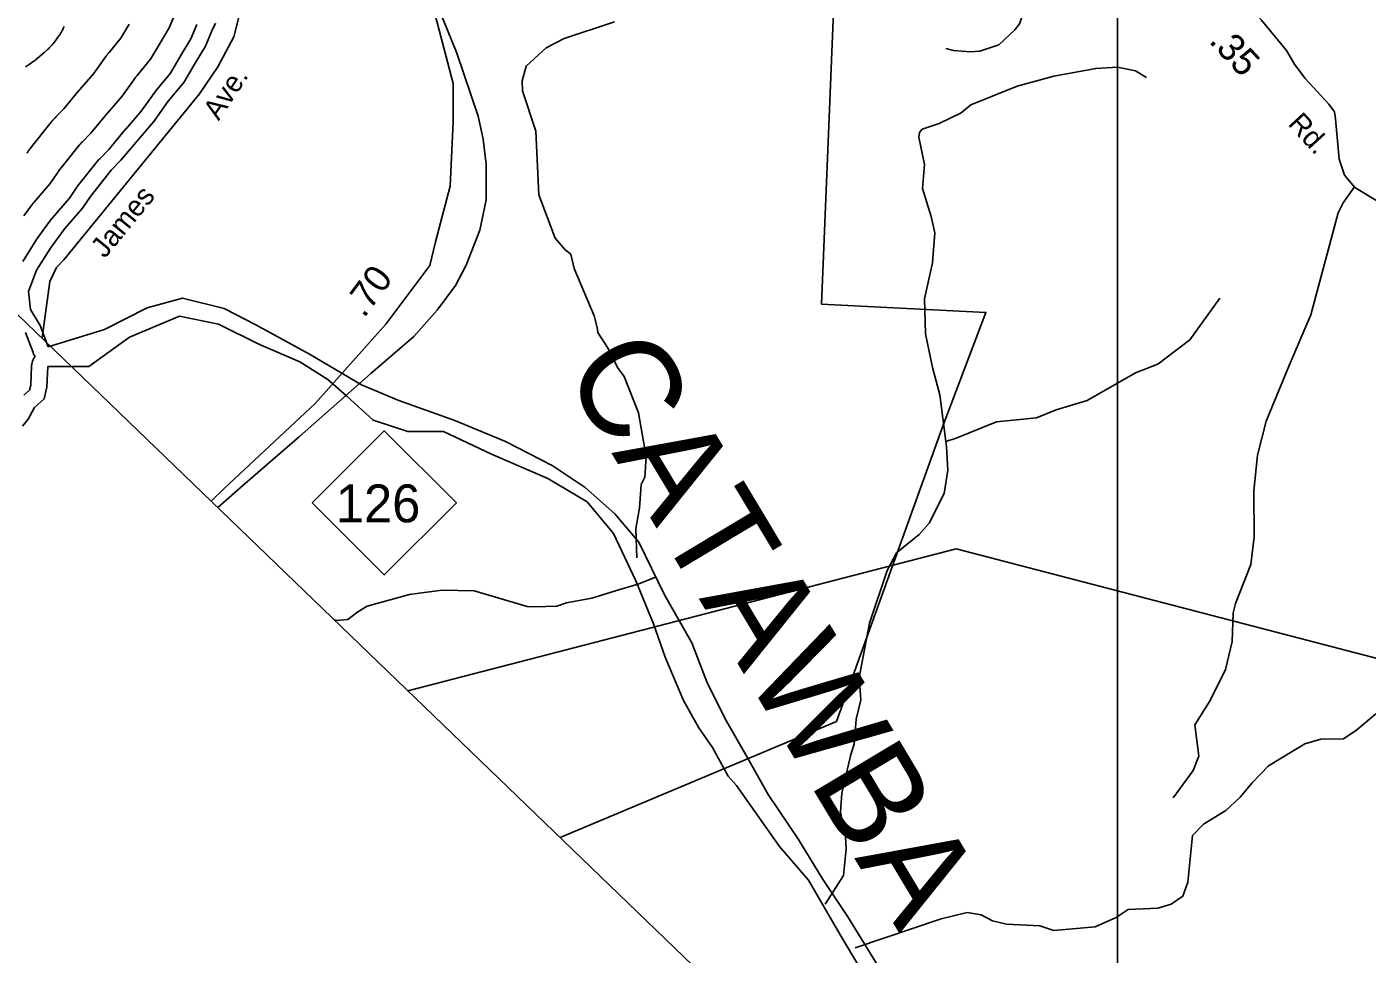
# Model space of a CAD drawing. Extents: x 1113032 to 1302912, y 664689 to 832535.
# Drawn here: x 1142627 to 1148822, y 731794 to 736082 of the extents above; entities that cross this region are included whole.
import ezdxf

# ---------------------------------------------------------------- set-up
doc = ezdxf.new("R2010")
doc.units = 0
for name, color, linetype in [('Exist Boundary Land Use Park State Division NC Parks and Recreation', 7, 'Continuous'), ('Exist Boundary Political CountyLine', 7, 'Continuous'), ('Exist Hydrographic Buffer Line', 7, 'Continuous'), ('Exist Hydrographic Lake Shore', 7, 'Continuous'), ('Exist Hydrographic Misc Water Feature', 7, 'Continuous'), ('Exist Hydrographic River Shore', 7, 'Continuous'), ('Exist Road Non-System Type 51', 7, 'Continuous'), ('Exist Road Non-System Type 51 Label', 7, 'Continuous'), ('Exist Road Primary NC Attributed', 7, 'Continuous'), ('Exist Road Primary NC Mileage Hundredths English Label', 7, 'Continuous'), ('Exist Road Primary NC Shield CELL', 7, 'Continuous'), ('Exist Road Primary NC Shield Number Label', 7, 'Continuous'), ('Exist Road Secondary Mileage Hundredths English Label', 7, 'Continuous'), ('Exist Road Secondary Type 51 Attributed', 7, 'Continuous'), ('Exist Road Secondary Type 51 Label', 7, 'Continuous'), ('Exist Utilities Electrical Transmission Line', 7, 'Continuous'), ('Map Preparation Inset Cut Line', 7, 'Continuous')]:
    doc.layers.add(name, color=color, linetype=linetype)

msp = doc.modelspace()

# ---------------------------------------------------------------- linework, layer by layer
at = {"layer": 'Exist Boundary Land Use Park State Division NC Parks and Recreation'}
for points in [[(1146388.6, 736979.2), (1146300.2, 734800.2), (1147059.9, 734761.5), (1146861.6, 734240.6), (1146368.8, 732870.4), (1145091.6, 732333.9)], [(1143478.9, 733889.6), (1143539.3, 733947.8), (1143959.8, 734341.2), (1144285.5, 734707.5), (1144489, 734978.9), (1144516, 735087.4), (1144583.9, 735345.1), (1144597.6, 735643.6), (1144597.6, 735820), (1144516, 736132)]]:
    msp.add_lwpolyline(points, dxfattribs=at)
at = {"layer": 'Exist Boundary Political CountyLine'}
msp.add_lwpolyline([(1114483.4, 761940.5), (1121830, 755020.9), (1129762.4, 747574.8), (1131998.8, 745469.7), (1132534.3, 744969.6), (1136601.4, 740850.7), (1137713.1, 739712.4), (1140850.4, 736412.5), (1141222.5, 736061.4), (1141222.5, 736061.4), (1142712.2, 734629.3), (1146816.8, 730669.7), (1148404.8, 729149.7)], dxfattribs=at)
at = {"layer": 'Exist Hydrographic Buffer Line'}
for points in [[(1142612.6, 735207.6), (1142651.1, 735260.2), (1142651.8, 735261.2), (1142652.5, 735262.1), (1142654.4, 735264.5), (1142655.8, 735266.3), (1142657.2, 735268.1), (1142659.2, 735270.5), (1142659.9, 735271.3), (1142660.7, 735272.2), (1142735.1, 735358.1), (1142765.5, 735403), (1142766.1, 735403.9), (1142766.7, 735404.7), (1142768.3, 735407.1), (1142769.6, 735408.8), (1142770.8, 735410.5), (1142772.6, 735412.8), (1142773.2, 735413.6), (1142773.9, 735414.5), (1142870.6, 735536.2), (1142871.5, 735537.3), (1142872.4, 735538.5), (1142874.9, 735541.5), (1142876.8, 735543.7), (1142878.8, 735545.9), (1142881.5, 735548.7), (1142882.5, 735549.8), (1142883.5, 735550.9), (1142922.7, 735590.9), (1142996.9, 735680), (1142997, 735680.2), (1142997.2, 735680.4), (1142997.6, 735680.9), (1142998, 735681.3), (1142998.3, 735681.7), (1142998.7, 735682.2), (1142998.9, 735682.4), (1142999.1, 735682.6), (1143066.7, 735760.9), (1143128.7, 735847.2), (1143129.2, 735847.9), (1143129.8, 735848.7), (1143131.3, 735850.7), (1143132.4, 735852.2), (1143133.6, 735853.7), (1143135.2, 735855.6), (1143135.7, 735856.4), (1143136.3, 735857.1), (1143199, 735933), (1143244.5, 736009.5), (1143284.7, 736077.7), (1143309.8, 736136.8)], [(1142607.6, 734996.6), (1142672, 735098.8), (1142673.4, 735101), (1142674.9, 735103.1), (1142702.9, 735141.4), (1142702.9, 735141.4), (1142703, 735141.4), (1142741.5, 735194.1), (1142743.4, 735196.5), (1142745.3, 735198.9), (1142824.1, 735289.8), (1142858.2, 735340.2), (1142859.9, 735342.5), (1142861.6, 735344.8), (1142958.3, 735466.6), (1142960.8, 735469.6), (1142963.5, 735472.4), (1143005.9, 735515.7), (1143083, 735608.4), (1143083.4, 735608.9), (1143083.9, 735609.4), (1143154.7, 735691.5), (1143219.6, 735781.8), (1143221.1, 735783.8), (1143222.7, 735785.8), (1143290.9, 735868.3), (1143340.8, 735952.4), (1143384.9, 736027.1), (1143412.9, 736093.1)], [(1142799.4, 736083.4), (1142798.3, 736081), (1142795.1, 736074.5), (1142792.7, 736069.7), (1142790.1, 736064.9), (1142786.6, 736058.7), (1142785.2, 736056.4), (1142783.8, 736054), (1142778.8, 736045.8), (1142777.4, 736043.5), (1142775.9, 736041.3), (1142772, 736035.2), (1142769, 736030.8), (1142765.8, 736026.4), (1142761.5, 736020.7), (1142759.9, 736018.5), (1142758.2, 736016.4), (1142752.2, 736008.9), (1142750.5, 736006.8), (1142748.7, 736004.7), (1142744, 735999.3), (1142740.5, 735995.2), (1142736.8, 735991.3), (1142731.7, 735986.2), (1142729.9, 735984.2), (1142727.9, 735982.4), (1142721, 735975.7), (1142720, 735974.7), (1142719, 735973.8), (1142716.4, 735971.4), (1142714.4, 735969.5), (1142712.4, 735967.8), (1142709.7, 735965.4), (1142708.7, 735964.5), (1142707.6, 735963.6), (1142671.7, 735933.2), (1142670.6, 735932.3), (1142669.5, 735931.3), (1142666.5, 735928.9), (1142664.2, 735927.1), (1142662, 735925.4), (1142658.9, 735923), (1142657.8, 735922.2), (1142656.6, 735921.3), (1142648.4, 735915.2), (1142646, 735913.6), (1142643.7, 735911.9), (1142637.3, 735907.6), (1142632.5, 735904.4), (1142627.6, 735901.4), (1142621, 735897.6)], [(1142626.6, 735497.5), (1142626.8, 735497.8), (1142627.4, 735498.7), (1142627.8, 735499.3), (1142628.3, 735500), (1142628.9, 735500.9), (1142629.1, 735501.2), (1142629.4, 735501.5), (1142631, 735503.9), (1142631.5, 735504.5), (1142631.9, 735505.2), (1142633.2, 735506.9), (1142634.1, 735508.2), (1142635.1, 735509.5), (1142636.3, 735511.2), (1142636.8, 735511.8), (1142637.3, 735512.5), (1142639, 735514.7), (1142639.3, 735515), (1142639.5, 735515.4), (1142640.2, 735516.2), (1142640.7, 735516.8), (1142641.2, 735517.5), (1142641.8, 735518.3), (1142642.1, 735518.6), (1142642.3, 735518.9), (1142739, 735640.7), (1142739.3, 735641.1), (1142739.7, 735641.5), (1142740.6, 735642.7), (1142741.3, 735643.5), (1142742, 735644.4), (1142742.9, 735645.5), (1142743.3, 735645.9), (1142743.6, 735646.4), (1142746.1, 735649.4), (1142746.9, 735650.2), (1142747.6, 735651), (1142749.5, 735653.3), (1142750.9, 735654.9), (1142752.4, 735656.5), (1142754.4, 735658.7), (1142755.1, 735659.5), (1142755.8, 735660.3), (1142758.5, 735663.2), (1142758.9, 735663.6), (1142759.3, 735664), (1142760.3, 735665.1), (1142761, 735665.9), (1142761.8, 735666.7), (1142762.8, 735667.7), (1142763.2, 735668.1), (1142763.6, 735668.5), (1142798, 735703.6), (1142867.7, 735787.4), (1142867.8, 735787.5), (1142867.8, 735787.6), (1142868, 735787.8), (1142868.1, 735787.9), (1142868.2, 735788.1), (1142868.4, 735788.2), (1142868.5, 735788.3), (1142868.5, 735788.4), (1142869, 735788.9), (1142869.1, 735789.1), (1142869.2, 735789.2), (1142869.5, 735789.6), (1142869.8, 735789.9), (1142870, 735790.2), (1142870.3, 735790.5), (1142870.5, 735790.7), (1142870.6, 735790.8), (1142871, 735791.3), (1142871.1, 735791.4), (1142871.1, 735791.5), (1142871.3, 735791.7), (1142871.4, 735791.8), (1142871.5, 735792), (1142871.7, 735792.1), (1142871.8, 735792.2), (1142871.8, 735792.3), (1142934.6, 735865.1), (1142992.3, 735945.3), (1142992.5, 735945.6), (1142992.7, 735945.9), (1142993.3, 735946.6), (1142993.7, 735947.2), (1142994.1, 735947.7), (1142994.7, 735948.5), (1142994.9, 735948.8), (1142995.1, 735949.1), (1142996.6, 735951.1), (1142997, 735951.6), (1142997.4, 735952.2), (1142998.6, 735953.7), (1142999.4, 735954.8), (1143000.3, 735955.9), (1143001.4, 735957.4), (1143001.9, 735958), (1143002.3, 735958.5), (1143003.9, 735960.5), (1143004.1, 735960.7), (1143004.3, 735961), (1143004.9, 735961.7), (1143005.3, 735962.3), (1143005.8, 735962.8), (1143006.4, 735963.6), (1143006.6, 735963.8), (1143006.8, 735964.1), (1143061.2, 736029.9), (1143099.9, 736095.1)], [(1142613.1, 734379.7), (1142639.5, 734402.4), (1142644.8, 734426), (1142649.1, 734515.3), (1142649.8, 734522.7), (1142651.3, 734529.9), (1142653.4, 734536.9), (1142656.2, 734543.7), (1142659.7, 734550.2), (1142663.8, 734556.3), (1142665.1, 734557.9), (1142661.9, 734562.5), (1142658.3, 734568.9), (1142655.4, 734575.7), (1142620.5, 734668.6)]]:
    msp.add_lwpolyline(points, dxfattribs=at)
at = {"layer": 'Exist Hydrographic Lake Shore'}
for points in [[(1143498.4, 736099.6), (1143482, 736063.8), (1143452, 735993.2), (1143405.4, 735914.2), (1143352.4, 735825), (1143280.5, 735738), (1143213.7, 735645.1), (1143140.7, 735560.4), (1143061.6, 735465.4), (1143017, 735419.9), (1142920.3, 735298.2), (1142883.7, 735244.1), (1142802, 735149.8), (1142763.5, 735097.1), (1142735.5, 735058.8), (1142671.1, 734956.6), (1142633.9, 734858.1), (1142643.6, 734774.5), (1142688.2, 734701.7), (1142725.6, 734602)], [(1142724, 734511.7), (1142719.4, 734416), (1142707.3, 734361.8), (1142662, 734322.8), (1142633.2, 734267.6), (1142607.4, 734236.4)]]:
    msp.add_lwpolyline(points, dxfattribs=at)
at = {"layer": 'Exist Hydrographic Misc Water Feature'}
for p, q in [((1146922.4, 734179.6), (1146874.7, 734164.2)), ((1146853.5, 731958), (1146454.7, 731823.6))]:
    msp.add_line(p, q, dxfattribs=at)
for points in [[(1145342.6, 736105.8), (1145110.3, 736028.6), (1145026.8, 735985), (1144934.3, 735899.7), (1144916.2, 735832.2), (1144917, 735786.2), (1144979.5, 735600.2), (1144992.8, 735305.6), (1145068.9, 735105.2), (1145115.4, 735051.8), (1145140.7, 735031), (1145156.9, 734964.4), (1145248.4, 734745.6), (1145262.7, 734691.2), (1145266.1, 734669.1), (1145314, 734595.6), (1145357.4, 734506.3), (1145388.2, 734465.3), (1145453.2, 734297.3), (1145489.3, 734094.1), (1145482.6, 734000.2), (1145465.5, 733966.7), (1145458.3, 733856.8), (1145441.5, 733763.2), (1145446.7, 733627)], [(1147802.1, 735847.4), (1147750.9, 735878.8), (1147667.4, 735895.3), (1147567.2, 735889.9), (1147374.1, 735853.5), (1147204.7, 735808.5), (1146990.4, 735720.8)], [(1146990.4, 735720.8), (1146945.3, 735684.2), (1146843.8, 735635.2), (1146765.1, 735609.5), (1146752.5, 735593.7), (1146749.9, 735571.9), (1146776.1, 735445), (1146766.9, 735335.2), (1146807.1, 735205.9), (1146822.8, 735129.4), (1146812.8, 734991.6), (1146775.8, 734824.5), (1146781, 734662.3), (1146812.4, 734507.2), (1146846.7, 734380.2), (1146874.7, 734164.2)], [(1148141.6, 734827.2), (1148002, 734634.7), (1147854.7, 734522.8), (1147751.6, 734482.2), (1147527.7, 734354.6), (1147384.5, 734310.6), (1147293.4, 734274.7), (1147108.7, 734256.2), (1146922.4, 734179.6)], [(1146874.7, 734164.2), (1146877.6, 734141.1), (1146884.4, 734032.8), (1146867.3, 733925.2), (1146797.1, 733787.2), (1146751.5, 733734.5), (1146647, 733649.6), (1146602.6, 733568.8), (1146521.3, 733325), (1146474, 733074.3), (1146480.9, 732970), (1146460.1, 732880.5), (1146450.7, 732764.7), (1146435.3, 732717.2), (1146393.9, 732538.2), (1146387.5, 732450.4), (1146397.7, 732394.1), (1146409, 732365.7), (1146414.4, 732281.5), (1146400.7, 732157.8), (1146317, 732025)], [(1145531.8, 733538.2), (1145451.9, 733504.7), (1145367.1, 733481.2), (1145237.9, 733441.1), (1145121.2, 733418.5), (1145076.7, 733403.8), (1144976.5, 733400.7), (1144938.6, 733401.8), (1144694.5, 733475.1), (1144544.5, 733477.6), (1144395.8, 733457.9), (1144200.1, 733403.6), (1144157.3, 733376.9), (1144110.1, 733342.3), (1144056, 733337.9), (1144048.6, 733340)], [(1148861.7, 732905.8), (1148773.5, 732832), (1148712.2, 732789.8), (1148608.3, 732788.6), (1148533.5, 732767.1), (1148366.5, 732665.4), (1148290.3, 732587.3), (1148234.4, 732521.1), (1148168.5, 732459.3), (1148064.7, 732395.7), (1148015.2, 732343.4), (1147993.1, 732128), (1147969.2, 732062), (1147916.2, 732026.1), (1147853.7, 732007.7), (1147717.3, 732001.4), (1147662.4, 731964.8), (1147565.1, 731921.6), (1147374.3, 731903.2), (1147309, 731925.1), (1147155.1, 731933.1), (1147089.4, 731949.1), (1147038.2, 731976.4), (1146972.5, 731986.8), (1146853.5, 731958)]]:
    msp.add_lwpolyline(points, dxfattribs=at)
at = {"layer": 'Exist Hydrographic River Shore'}
for points in [[(1142725.6, 734602), (1142986.3, 734682.8), (1143182.4, 734782.7), (1143346.2, 734827.2), (1143538.9, 734779.4), (1143685.9, 734704.2), (1143932.7, 734569.3), (1144174.2, 734426.7), (1144346.5, 734354.5), (1144604.4, 734262.4), (1144839.5, 734164.3)], [(1146602.7, 731519.1), (1146384.8, 731886.4), (1146240, 732137.3), (1146105, 732291.7), (1145907.6, 732573.6), (1145868.3, 732617.4), (1145795.5, 732750.1), (1145732.5, 732841.1), (1145661.8, 732966.6), (1145577.1, 733168.4), (1145523.5, 733322), (1145441.3, 733521.4), (1145338.7, 733740.1), (1145216.7, 733885.3), (1145035.2, 733994.4), (1144774.5, 734106), (1144553, 734211.1), (1144388.5, 734210.5), (1144227.1, 734262.9), (1144105.6, 734374.1), (1144018.3, 734451.1), (1143888, 734532.8), (1143701.8, 734612.6), (1143512.2, 734708.1), (1143331.8, 734745.1), (1143101.5, 734646.8), (1142913.5, 734512), (1142724, 734511.7)], [(1144839.5, 734164.3), (1145054.2, 734053.3), (1145207.4, 733951.7), (1145344.9, 733829.7), (1145456.1, 733699.6), (1145574, 733456.6), (1145700.6, 733233.7), (1145770.2, 733053.4), (1145854.4, 732881.9), (1145956.8, 732704.6), (1146053.7, 732532.4), (1146193.5, 732325.1), (1146304.9, 732142.9), (1146421.8, 731967.2), (1146635.2, 731618.5)]]:
    msp.add_lwpolyline(points, dxfattribs=at)
at = {"layer": 'Exist Road Non-System Type 51'}
for points in [[(1146874, 735982.4), (1146909.6, 735973.1), (1146986.9, 735966.3), (1147030.9, 735969.1), (1147119.8, 735998.8), (1147193.8, 736068.5), (1147214.7, 736096), (1147244.8, 736177.2), (1147276.2, 736218.5), (1147296.5, 736231.9), (1147384.4, 736231.5), (1147445, 736241.7), (1147639.3, 736322.2), (1147779.8, 736338.4), (1147826.8, 736372.9), (1147884.3, 736427.3), (1147964, 736524)], [(1143616.3, 736225.2), (1143608.1, 736132.8), (1143583.2, 736035.5), (1143509.2, 735897.8), (1143425.3, 735772.1), (1142798.1, 735004.1), (1142763.3, 734969), (1142733.1, 734904), (1142696.9, 734644)], [(1147925.8, 732517.5), (1148017.6, 732643), (1148043.6, 732710.4), (1148025.4, 732854.9), (1148096.6, 732967), (1148166.8, 733111.4), (1148198.6, 733240.4), (1148202.2, 733372.3), (1148213.6, 733416), (1148284.5, 733596.1), (1148300.2, 733723.8), (1148298.2, 733936.2), (1148315, 734101.6), (1148355.5, 734258.7), (1148460.8, 734515.9), (1148561.4, 734751.2), (1148687, 735222), (1148710.3, 735269.1), (1148762.7, 735342.2)]]:
    msp.add_lwpolyline(points, dxfattribs=at)
at = {"layer": 'Exist Road Primary NC Attributed'}
msp.add_lwpolyline([(1143509.8, 733859.8), (1143625.8, 733961.1), (1143887.5, 734188.4), (1144216, 734479.6), (1144415.3, 734650.6), (1144523.7, 734771.5), (1144608.6, 734886), (1144658, 734980.3), (1144720.4, 735142.7), (1144749.2, 735281.6), (1144750.4, 735447.2), (1144735.6, 735563.4), (1144713.5, 735668.6), (1144615, 735960.5), (1144481, 736288.4), (1144417.9, 736456.7), (1144382.8, 736612.6), (1144360.2, 736761.6), (1144341.8, 736941.4)], dxfattribs=at)
at = {"layer": 'Exist Road Primary NC Shield CELL'}
msp.add_lwpolyline([(1143946, 733881.1), (1144279, 734214.1), (1144612, 733881.1), (1144279, 733548.1)], close=True, dxfattribs=at)
at = {"layer": 'Exist Road Secondary Type 51 Attributed'}
msp.add_lwpolyline([(1149107.9, 735268.3), (1148972.9, 735265.7), (1148869.5, 735276), (1148765.2, 735339.3), (1148717.3, 735395.7), (1148692, 735470), (1148675.6, 735657.1), (1148671.4, 735688.7), (1148645.1, 735725.3), (1148534.7, 735842.9), (1148485.2, 735909.6), (1148449.3, 735972), (1148333.2, 736113.6), (1148257.9, 736195.7), (1148192.6, 736248.2), (1148127.7, 736307), (1148057.6, 736382.3), (1147961.9, 736527.3), (1147905.4, 736636.1)], dxfattribs=at)
at = {"layer": 'Exist Utilities Electrical Transmission Line'}
msp.add_lwpolyline([(1144388.3, 733012.3), (1146921.8, 733668.7), (1152275.9, 732274.5), (1155913.5, 733164.3), (1157133.3, 734480.7), (1157461, 735732.3), (1158252.1, 736454.4), (1158222.6, 737177.7)], dxfattribs=at)
at = {"layer": 'Map Preparation Inset Cut Line'}
msp.add_lwpolyline([(1223351.7, 748878.2), (1147668.5, 748878.2), (1147668.5, 704629.7), (1208143, 704629.7), (1208143, 720169.6), (1223351.7, 720169.6)], close=True, dxfattribs=at)

# ---------------------------------------------------------------- texts
at = {"layer": 'Exist Hydrographic Lake Shore'}
msp.add_text('CATAWBA', height=459.32, rotation=300.93036, dxfattribs=at).set_placement((1145099.9, 734492.9))
at = {"layer": 'Exist Road Non-System Type 51 Label'}
for s, rotation, p in [('Ave.', 56.26784, (1143513.6, 735644.7)), ('James', 50.76189, (1142987.4, 735007.9))]:
    msp.add_text(s, height=95, rotation=rotation, dxfattribs=at).set_placement(p)
at = {"layer": 'Exist Road Primary NC Mileage Hundredths English Label'}
msp.add_text('.70', height=125, rotation=53.43318, dxfattribs=at).set_placement((1144185.1, 734732.2))
at = {"layer": 'Exist Road Primary NC Shield Number Label'}
msp.add_text('126', height=175, dxfattribs=at).set_placement((1144055.1, 733791.3))
at = {"layer": 'Exist Road Secondary Mileage Hundredths English Label'}
msp.add_text('.35', height=125, rotation=312.94442, dxfattribs=at).set_placement((1148086.6, 736013.4))
at = {"layer": 'Exist Road Secondary Type 51 Label'}
msp.add_text('Rd.', height=95, rotation=312.51046, dxfattribs=at).set_placement((1148451.6, 735631))

doc.saveas('drawing.dxf')
